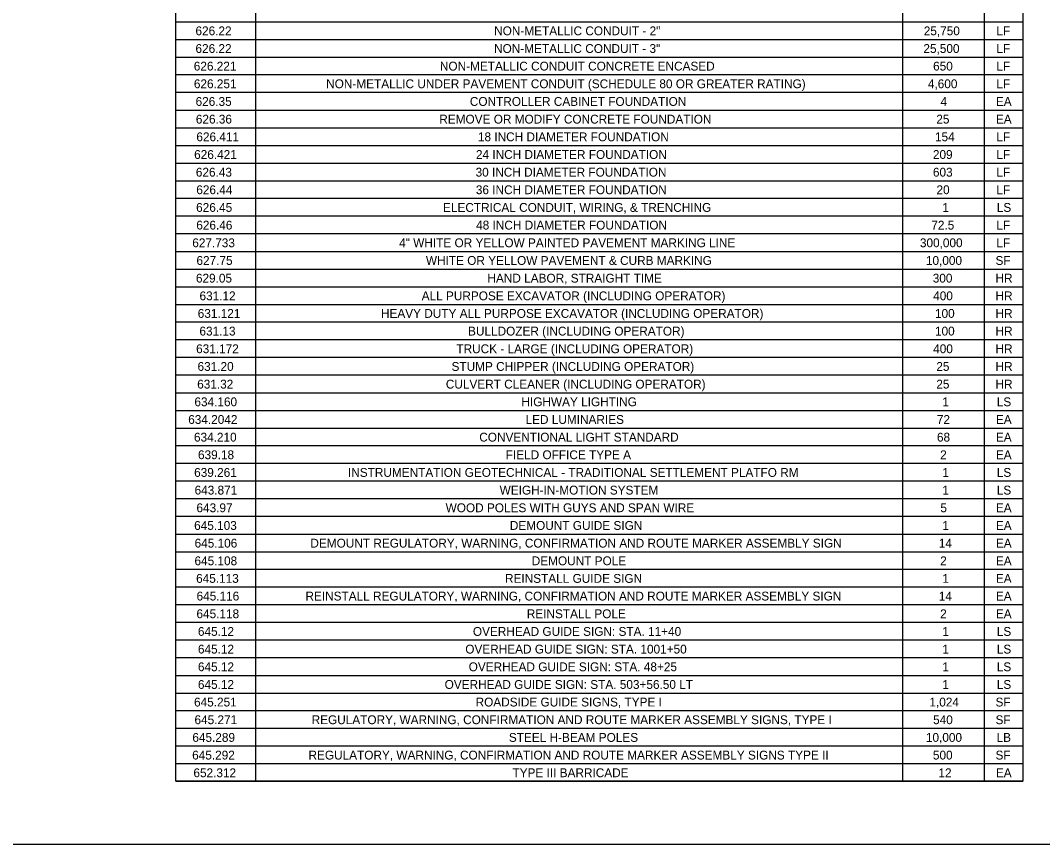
# Model space of a CAD drawing. Extents: x -18.7 to 5.6, y -2.7 to 5.1.
# Drawn here: x -15.505 to -14.366, y 2.172 to 3.09 of the extents above; entities that cross this region are included whole.
import ezdxf

# ---------------------------------------------------------------- set-up
doc = ezdxf.new("R2010")
doc.units = 0
doc.layers.add('ANNOTATION', color=7, linetype='Continuous')
doc.layers.add('BORDER', color=7, linetype='Continuous')

msp = doc.modelspace()

# ---------------------------------------------------------------- linework, layer by layer
at = {"layer": 'ANNOTATION'}
msp.add_lwpolyline([(-17.663, 4.0141), (-13.3075, 4.0141), (-13.3075, 2.1719), (-17.663, 2.1719)], close=True, dxfattribs=at)
at = {"layer": 'BORDER'}
for p, q in [((-15.2435, 3.9551), (-15.2435, 2.2424)), ((-14.5222, 3.9551), (-14.5222, 2.2424)), ((-14.4308, 3.9551), (-14.4308, 2.2424)), ((-15.3321, 3.0889), (-14.3878, 3.0889)), ((-15.3321, 3.0692), (-14.3878, 3.0692)), ((-15.3321, 3.0495), (-14.3878, 3.0495)), ((-15.3321, 3.0299), (-14.3878, 3.0299)), ((-15.3321, 3.0102), (-14.3878, 3.0102)), ((-15.3321, 2.9905), (-14.3878, 2.9905)), ((-15.3321, 2.9708), (-14.3878, 2.9708)), ((-15.3321, 2.9511), (-14.3878, 2.9511)), ((-15.3321, 2.9314), (-14.3878, 2.9314)), ((-15.3321, 2.9117), (-14.3878, 2.9117)), ((-15.3321, 2.8921), (-14.3878, 2.8921)), ((-15.3321, 2.8724), (-14.3878, 2.8724)), ((-15.3321, 2.8527), (-14.3878, 2.8527)), ((-15.3321, 2.833), (-14.3878, 2.833)), ((-15.3321, 2.8133), (-14.3878, 2.8133)), ((-15.3321, 2.7936), (-14.3878, 2.7936)), ((-15.3321, 2.7739), (-14.3878, 2.7739)), ((-15.3321, 2.7543), (-14.3878, 2.7543)), ((-15.3321, 2.7346), (-14.3878, 2.7346)), ((-15.3321, 2.7149), (-14.3878, 2.7149)), ((-15.3321, 2.6952), (-14.3878, 2.6952)), ((-15.3321, 2.6755), (-14.3878, 2.6755)), ((-15.3321, 2.6558), (-14.3878, 2.6558)), ((-15.3321, 2.6361), (-14.3878, 2.6361)), ((-15.3321, 2.6165), (-14.3878, 2.6165)), ((-15.3321, 2.5968), (-14.3878, 2.5968)), ((-15.3321, 2.5771), (-14.3878, 2.5771)), ((-15.3321, 2.5574), (-14.3878, 2.5574)), ((-15.3321, 2.5377), (-14.3878, 2.5377)), ((-15.3321, 2.518), (-14.3878, 2.518)), ((-15.3321, 2.4983), (-14.3878, 2.4983)), ((-15.3321, 2.4787), (-14.3878, 2.4787)), ((-15.3321, 2.459), (-14.3878, 2.459)), ((-15.3321, 2.4393), (-14.3878, 2.4393)), ((-15.3321, 2.4196), (-14.3878, 2.4196)), ((-15.3321, 2.3999), (-14.3878, 2.3999)), ((-15.3321, 2.3802), (-14.3878, 2.3802)), ((-15.3321, 2.3605), (-14.3878, 2.3605)), ((-15.3321, 2.3408), (-14.3878, 2.3408)), ((-15.3321, 2.3212), (-14.3878, 2.3212)), ((-15.3321, 2.3015), (-14.3878, 2.3015)), ((-15.3321, 2.2818), (-14.3878, 2.2818)), ((-15.3321, 2.2621), (-14.3878, 2.2621)), ((-15.3321, 2.2424), (-14.3878, 2.2424))]:
    msp.add_line(p, q, dxfattribs=at)
msp.add_lwpolyline([(-15.3321, 3.9748), (-14.3878, 3.9748), (-14.3878, 2.2424), (-15.3321, 2.2424)], close=True, dxfattribs=at)

# ---------------------------------------------------------------- texts
at = {"layer": 'ANNOTATION'}
for s, height, p in [('626.22', 0.00984, (-15.3103, 3.0738)), ('NON-METALLIC CONDUIT - 2"', 0.009843, (-14.9773, 3.0738)), ('25,750', 0.00984, (-14.4983, 3.0738)), ('LF', 0.00984, (-14.4173, 3.0738)), ('626.22', 0.00984, (-15.3103, 3.0541)), ('NON-METALLIC CONDUIT - 3"', 0.009843, (-14.9774, 3.0541)), ('25,500', 0.00984, (-14.4987, 3.0541)), ('LF', 0.00984, (-14.4173, 3.0541)), ('626.221', 0.00984, (-15.3122, 3.0345)), ('NON-METALLIC CONDUIT CONCRETE ENCASED', 0.009843, (-15.0378, 3.0345)), ('650', 0.00984, (-14.4879, 3.0345)), ('LF', 0.00984, (-14.4173, 3.0345)), ('626.251', 0.00984, (-15.3121, 3.0148)), ('NON-METALLIC UNDER PAVEMENT CONDUIT (SCHEDULE 80 OR GREATER RATING)', 0.009843, (-15.1646, 3.0148)), ('4,600', 0.00984, (-14.4937, 3.0148)), ('LF', 0.00984, (-14.4173, 3.0148)), ('626.35', 0.00984, (-15.3102, 2.9951)), ('CONTROLLER CABINET FOUNDATION', 0.009843, (-15.0044, 2.9951)), ('4', 0.00984, (-14.4796, 2.9951)), ('EA', 0.00984, (-14.4179, 2.9951)), ('626.36', 0.00984, (-15.3099, 2.9754)), ('REMOVE OR MODIFY CONCRETE FOUNDATION', 0.009843, (-15.0385, 2.9754)), ('25', 0.00984, (-14.4843, 2.9754)), ('EA', 0.00984, (-14.4179, 2.9754)), ('626.411', 0.00984, (-15.3093, 2.9557)), ('18 INCH DIAMETER FOUNDATION', 0.009843, (-14.9954, 2.9557)), ('154', 0.00984, (-14.4858, 2.9557)), ('LF', 0.00984, (-14.4173, 2.9557)), ('626.421', 0.00984, (-15.3118, 2.936)), ('24 INCH DIAMETER FOUNDATION', 0.009843, (-14.9976, 2.936)), ('209', 0.00984, (-14.4881, 2.936)), ('LF', 0.00984, (-14.4173, 2.936)), ('626.43', 0.00984, (-15.3099, 2.9163)), ('30 INCH DIAMETER FOUNDATION', 0.009843, (-14.998, 2.9163)), ('603', 0.00984, (-14.4881, 2.9163)), ('LF', 0.00984, (-14.4173, 2.9163)), ('626.44', 0.00984, (-15.3094, 2.8967)), ('36 INCH DIAMETER FOUNDATION', 0.009843, (-14.9977, 2.8967)), ('20', 0.00984, (-14.4841, 2.8967)), ('LF', 0.00984, (-14.4173, 2.8967)), ('626.45', 0.00984, (-15.3096, 2.877)), ('ELECTRICAL CONDUIT, WIRING, & TRENCHING', 0.009843, (-15.0343, 2.877)), ('1', 0.00984, (-14.4776, 2.877)), ('LS', 0.00984, (-14.4169, 2.877)), ('626.46', 0.00984, (-15.3094, 2.8573)), ('48 INCH DIAMETER FOUNDATION', 0.009843, (-14.9974, 2.8573)), ('72.5', 0.00984, (-14.4899, 2.8573)), ('LF', 0.00984, (-14.4173, 2.8573)), ('627.733', 0.00984, (-15.3139, 2.8376)), ('4" WHITE OR YELLOW PAINTED PAVEMENT MARKING LINE', 0.009843, (-15.0832, 2.8376)), ('300,000', 0.00984, (-14.5026, 2.8376)), ('LF', 0.00984, (-14.4173, 2.8376)), ('627.75', 0.00984, (-15.3092, 2.8179)), ('WHITE OR YELLOW PAVEMENT & CURB MARKING', 0.009843, (-15.0534, 2.8179)), ('10,000', 0.00984, (-14.4959, 2.8179)), ('SF', 0.00984, (-14.4183, 2.8179)), ('629.05', 0.00984, (-15.3098, 2.7982)), ('HAND LABOR, STRAIGHT TIME', 0.009843, (-14.9848, 2.7982)), ('300', 0.00984, (-14.4883, 2.7982)), ('HR', 0.00984, (-14.4183, 2.7982)), ('631.12', 0.00984, (-15.3058, 2.7785)), ('ALL PURPOSE EXCAVATOR (INCLUDING OPERATOR)', 0.009843, (-15.0581, 2.7785)), ('400', 0.00984, (-14.4878, 2.7785)), ('HR', 0.00984, (-14.4183, 2.7785)), ('631.121', 0.00984, (-15.3078, 2.7589)), ('HEAVY DUTY ALL PURPOSE EXCAVATOR (INCLUDING OPERATOR)', 0.009843, (-15.1035, 2.7589)), ('100', 0.00984, (-14.4858, 2.7589)), ('HR', 0.00984, (-14.4183, 2.7589)), ('631.13', 0.00984, (-15.3059, 2.7392)), ('BULLDOZER (INCLUDING OPERATOR)', 0.009843, (-15.0064, 2.7392)), ('100', 0.00984, (-14.4858, 2.7392)), ('HR', 0.00984, (-14.4183, 2.7392)), ('631.172', 0.00984, (-15.3096, 2.7195)), ('TRUCK - LARGE (INCLUDING OPERATOR)', 0.009843, (-15.0194, 2.7195)), ('400', 0.00984, (-14.4878, 2.7195)), ('HR', 0.00984, (-14.4183, 2.7195)), ('631.20', 0.00984, (-15.308, 2.6998)), ('STUMP CHIPPER (INCLUDING OPERATOR)', 0.009843, (-15.0248, 2.6998)), ('25', 0.00984, (-14.4843, 2.6998)), ('HR', 0.00984, (-14.4183, 2.6998)), ('631.32', 0.00984, (-15.3084, 2.6801)), ('CULVERT CLEANER (INCLUDING OPERATOR)', 0.009843, (-15.0312, 2.6801)), ('25', 0.00984, (-14.4843, 2.6801)), ('HR', 0.00984, (-14.4183, 2.6801)), ('634.160', 0.00984, (-15.3115, 2.6604)), ('HIGHWAY LIGHTING', 0.009843, (-14.9469, 2.6604)), ('1', 0.00984, (-14.4776, 2.6604)), ('LS', 0.00984, (-14.4169, 2.6604)), ('634.2042', 0.00984, (-15.3184, 2.6407)), ('LED LUMINARIES', 0.009843, (-14.9423, 2.6407)), ('72', 0.00984, (-14.4837, 2.6407)), ('EA', 0.00984, (-14.4179, 2.6407)), ('634.210', 0.00984, (-15.312, 2.621)), ('CONVENTIONAL LIGHT STANDARD', 0.009843, (-14.9939, 2.621)), ('68', 0.00984, (-14.4836, 2.621)), ('EA', 0.00984, (-14.4179, 2.621)), ('639.18', 0.00984, (-15.3075, 2.6014)), ('FIELD OFFICE TYPE A', 0.009843, (-14.9644, 2.6014)), ('2', 0.00984, (-14.48, 2.6014)), ('EA', 0.00984, (-14.4179, 2.6014)), ('639.261', 0.00984, (-15.3118, 2.5817)), ('INSTRUMENTATION GEOTECHNICAL - TRADITIONAL SETTLEMENT PLATFO RM', 0.009843, (-15.1403, 2.5817)), ('1', 0.00984, (-14.4776, 2.5817)), ('LS', 0.00984, (-14.4169, 2.5817)), ('643.871', 0.00984, (-15.3113, 2.562)), ('WEIGH-IN-MOTION SYSTEM', 0.009843, (-14.9712, 2.562)), ('1', 0.00984, (-14.4776, 2.562)), ('LS', 0.00984, (-14.4169, 2.562)), ('643.97', 0.00984, (-15.3092, 2.5423)), ('WOOD POLES WITH GUYS AND SPAN WIRE', 0.009843, (-15.0314, 2.5423)), ('5', 0.00984, (-14.4798, 2.5423)), ('EA', 0.00984, (-14.4179, 2.5423)), ('645.103', 0.00984, (-15.3118, 2.5226)), ('DEMOUNT GUIDE SIGN', 0.009843, (-14.9598, 2.5226)), ('1', 0.00984, (-14.4776, 2.5226)), ('EA', 0.00984, (-14.4179, 2.5226)), ('645.106', 0.00984, (-15.3113, 2.5029)), ('DEMOUNT REGULATORY, WARNING, CONFIRMATION AND ROUTE MARKER ASSEMBLY SIGN', 0.009843, (-15.1822, 2.5029)), ('14', 0.00984, (-14.4815, 2.5029)), ('EA', 0.00984, (-14.4179, 2.5029)), ('645.108', 0.00984, (-15.3114, 2.4832)), ('DEMOUNT POLE', 0.009843, (-14.9354, 2.4832)), ('2', 0.00984, (-14.48, 2.4832)), ('EA', 0.00984, (-14.4179, 2.4832)), ('645.113', 0.00984, (-15.3096, 2.4636)), ('REINSTALL GUIDE SIGN', 0.009843, (-14.9652, 2.4636)), ('1', 0.00984, (-14.4776, 2.4636)), ('EA', 0.00984, (-14.4179, 2.4636)), ('645.116', 0.00984, (-15.3091, 2.4439)), ('REINSTALL REGULATORY, WARNING, CONFIRMATION AND ROUTE MARKER ASSEMBLY SIGN', 0.009843, (-15.1877, 2.4439)), ('14', 0.00984, (-14.4815, 2.4439)), ('EA', 0.00984, (-14.4179, 2.4439)), ('645.118', 0.00984, (-15.3092, 2.4242)), ('REINSTALL POLE', 0.009843, (-14.9409, 2.4242)), ('2', 0.00984, (-14.48, 2.4242)), ('EA', 0.00984, (-14.4179, 2.4242)), ('645.12', 0.00984, (-15.3076, 2.4045)), ('OVERHEAD GUIDE SIGN: STA. 11+40', 0.009843, (-15.001, 2.4045)), ('1', 0.00984, (-14.4776, 2.4045)), ('LS', 0.00984, (-14.4169, 2.4045)), ('645.12', 0.00984, (-15.3076, 2.3848)), ('OVERHEAD GUIDE SIGN: STA. 1001+50', 0.009843, (-15.0095, 2.3848)), ('1', 0.00984, (-14.4776, 2.3848)), ('LS', 0.00984, (-14.4169, 2.3848)), ('645.12', 0.00984, (-15.3076, 2.3651)), ('OVERHEAD GUIDE SIGN: STA. 48+25', 0.009843, (-15.0057, 2.3651)), ('1', 0.00984, (-14.4776, 2.3651)), ('LS', 0.00984, (-14.4169, 2.3651)), ('645.12', 0.00984, (-15.3076, 2.3454)), ('OVERHEAD GUIDE SIGN: STA. 503+56.50 LT', 0.009843, (-15.0325, 2.3454)), ('1', 0.00984, (-14.4776, 2.3454)), ('LS', 0.00984, (-14.4169, 2.3454)), ('645.251', 0.00984, (-15.3119, 2.3258)), ('ROADSIDE GUIDE SIGNS, TYPE I', 0.009843, (-14.998, 2.3258)), ('1,024', 0.00984, (-14.492, 2.3258)), ('SF', 0.00984, (-14.4183, 2.3258)), ('645.271', 0.00984, (-15.3114, 2.3061)), ('REGULATORY, WARNING, CONFIRMATION AND ROUTE MARKER ASSEMBLY SIGNS, TYPE I', 0.009843, (-15.1808, 2.3061)), ('540', 0.00984, (-14.4879, 2.3061)), ('SF', 0.00984, (-14.4183, 2.3061)), ('645.289', 0.00984, (-15.3138, 2.2864)), ('STEEL H-BEAM POLES', 0.009843, (-14.9609, 2.2864)), ('10,000', 0.00984, (-14.4959, 2.2864)), ('LB', 0.00984, (-14.4171, 2.2864)), ('645.292', 0.00984, (-15.314, 2.2667)), ('REGULATORY, WARNING, CONFIRMATION AND ROUTE MARKER ASSEMBLY SIGNS TYPE II', 0.009843, (-15.1843, 2.2667)), ('500', 0.00984, (-14.4881, 2.2667)), ('SF', 0.00984, (-14.4183, 2.2667)), ('652.312', 0.00984, (-15.3126, 2.247)), ('TYPE III BARRICADE', 0.009843, (-14.9569, 2.247)), ('12', 0.00984, (-14.4819, 2.247)), ('EA', 0.00984, (-14.4179, 2.247))]:
    msp.add_text(s, height=height, dxfattribs=at).set_placement(p)

doc.saveas('drawing.dxf')
